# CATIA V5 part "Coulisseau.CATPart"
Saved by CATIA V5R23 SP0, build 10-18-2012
Part number: Coulisseau
Material "Aluminium": density 2710 kg/m3, Young's modulus 7e+10 Pa, Poisson ratio 0.346, thermal expansion 2.36e-05 1/K
Bounding box of the stored display mesh (mm): x -45 to 45, y 0 to 10, z 0 to 70
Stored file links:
  P:\eleve\Coulisseau.CATPart
  C:\Program Files\Dassault Systemes\B23\win_b64\startup\materials\French\Catalog.CATMaterial
  d:\catia_soft\intel_a\reffiles\standard\MetricThickPitch.txt
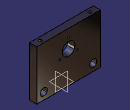
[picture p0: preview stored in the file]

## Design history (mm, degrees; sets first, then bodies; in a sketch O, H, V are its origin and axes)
Body1 (main body)
  Sketch1 on zx-plane, origin (0, 0, 0), H (-1, 0, 0), V (0, 0, 1)
    point P1 (-45, 0)
    line L1 (-45, 0) -> (45, 0)
    line L2 (45, 0) -> (45, 70)
    line L3 (45, 70) -> (-45, 70)
    line L4 (-45, 70) -> (-45, 0)
    reference intersected line E1 through (0, 0) direction (0, -1) from yz-plane
    distance L4 L2 = 90
    distance L1 L3 = 70
    coincidence: P1 H
    horizontal: L1 H, L3 H
    vertical: L2 V, L4 V
    symmetry: L4 L2 E1
  Pad1: profile Sketch1, direction (0, 1, 0), length 10
  Sketch2 on face of Pad1, origin (29.9594, 10, 15.624), H (1, 0, 0), V (0, 0, -1)
    point P1 (5.0406, 5.624)
    reference intersected line E1 through (-29.9594, 0) direction (0, 1) from yz-plane
    reference intersected line E2 (-74.9594, 15.624) -> (15.0406, 15.624) from face of Pad1
    distance E1 P1 = 35
    distance P1 E2 = 10
  Hole1: placed by Sketch2, at (35, 10, 10) direction (0, -1, 0), diameter 10, depth 10
  Mirror1: of Hole1, about yz-plane
  Sketch3 "Esquisse.3" on face of Pad1, origin (2.6151, 10, 57.1665), H (1, 0, 0), V (0, 0, -1)
    point P1 (-2.6151, 12.1665)
    reference intersected line E1 through (-2.6151, 0) direction (0, 1) from yz-plane
    reference intersected line E2 through (0, 57.1665) direction (1, 0) from xy-plane
    distance P1 E2 = 45
    coincidence: P1 E1
  Hole2 "Trou.2": placed by Sketch3, at (0, 10, 45) direction (0, -1, 0), diameter 18, depth 10
  Sketch4 "Esquisse.4" on face of Pad1, origin (-1.9622, 0, 63.3633), H (1, 0, 0), V (0, 0, 1)
    point P1 (1.9622, -4.3633)
    reference intersected line E1 through (1.9622, 0) direction (0, 1) from yz-plane
    reference projected point E2 (1.9622, -18.3633) from axis of face of Hole2
    distance P1 E2 = 14
    coincidence: E1 P1
  Hole3 "Trou.3": placed by Sketch4, at (0, 0, 59) direction (0, 1, 0), diameter 2.459, through (limit type 3), threaded "M3", thread diameter 3, thread depth 10, pitch 0.5
  CircPattern1: of Hole3, instances 3, angular step 120 {= 360.0*1 deg/CircPattern1.AngularNumber}, axis from face of Hole2
  Sketch5 "Esquisse.5" on face of Pad1, origin (29.0426, 4.5064, 70), H (1, 0, 0), V (0, 1, 0)
    point P1 (5.9574, 0.4936)
    reference intersected line E1 (15.9574, -4.5064) -> (-74.0426, -4.5064) from face of Pad1
    reference intersected line E2 (-74.0426, 5.4936) -> (15.9574, 5.4936) from face of Pad1
    reference intersected line E3 through (-29.0426, 0) direction (0, 1) from yz-plane
    distance P1 E3 = 35
    equidistance: E1 E2 P1
  Hole4 "Trou.4": placed by Sketch5, at (35, 5, 70) direction (0, 0, -1), diameter 4.134, depth 15, V-bottom angle 120, threaded "M5", thread diameter 5, thread depth 10, pitch 0.8
  Mirror2: of Hole4, about yz-plane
